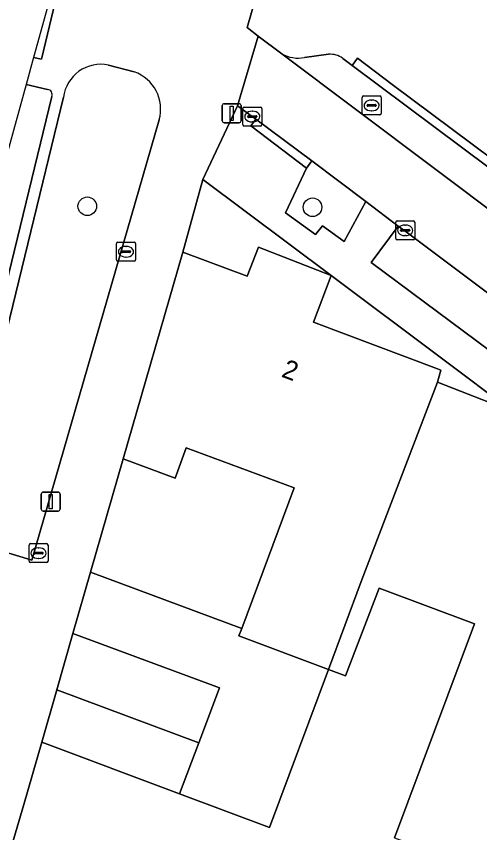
# Model space of a CAD drawing. Extents: x 163266 to 164362, y 381528 to 382286.
# Drawn here: x 163785.25 to 163809.64, y 382121.52 to 382164.49 of the extents above; entities that cross this region are included whole.
import ezdxf

# ---------------------------------------------------------------- set-up
doc = ezdxf.new("R2010")
doc.units = 0
for name, color, linetype in [('IMGEO_Boom', 7, 'Continuous'), ('IMGEO_Erf', 7, 'Continuous'), ('IMGEO_Groenvoorziening', 7, 'Continuous'), ('IMGEO_Kolk', 7, 'Continuous'), ('IMGEO_Lichtmast', 7, 'Continuous'), ('IMGEO_Muur', 7, 'Continuous'), ('IMGEO_Pand', 7, 'Continuous'), ('IMGEO_Pand_nummerreeks', 7, 'Continuous'), ('IMGEO_Parkeervlak_open', 7, 'Continuous'), ('IMGEO_Rijbaan_lokaal_open', 7, 'Continuous'), ('IMGEO_Rioolput', 7, 'Continuous'), ('IMGEO_Voetpad_open', 7, 'Continuous')]:
    doc.layers.add(name, color=color, linetype=linetype)

msp = doc.modelspace()

# ---------------------------------------------------------------- linework, layer by layer
at = {"layer": 'IMGEO_Boom'}
for centre in [(163788.984, 382154.488), (163800.841, 382154.435)]:
    msp.add_circle(centre, 0.489, dxfattribs=at)
at = {"layer": 'IMGEO_Erf'}
for points in [[(163795.065, 382155.894), (163794.02, 382152.073), (163797.406, 382150.806), (163798, 382152.33), (163801.822, 382150.851)], [(163811.358, 382143.691), (163807.624, 382146.494), (163801.822, 382150.851), (163800.894, 382148.381), (163807.412, 382145.926), (163807.598, 382145.856), (163807.41, 382145.221)], [(163797.111, 382132.268), (163799.881, 382139.668), (163794.196, 382141.767), (163793.603, 382140.172), (163790.866, 382141.191), (163789.158, 382135.228)]]:
    msp.add_lwpolyline(points, close=True, dxfattribs=at)
msp.add_lwpolyline([(163805.154, 382121.244), (163809.365, 382132.517), (163804.351, 382134.389), (163802.583, 382129.763), (163801.673, 382130.104), (163798.567, 382121.788), (163793.841, 382123.562), (163786.588, 382126.285), (163785.649, 382122.995), (163778.541, 382098.883)], dxfattribs=at)
at = {"layer": 'IMGEO_Groenvoorziening'}
for points in [[(163822.215, 382162.822), (163823.589, 382169.051), (163800.51, 382174.679), (163797.398, 382163.896), (163797.974, 382163.445), (163799.218, 382162.511)], [(163800.416, 382162.315), (163801.686, 382162.487)], [(163802.427, 382162.272), (163802.92, 382161.904), (163803.211, 382162.276), (163805.031, 382160.907), (163821.881, 382148.329)], [(163791.453, 382161.569), (163790.102, 382161.917)], [(163787.735, 382160.229), (163782.085, 382137.064), (163786.069, 382135.864), (163792.768, 382159.035)]]:
    msp.add_lwpolyline(points, dxfattribs=at)
for points in [[(163803.653, 382154.731), (163800.797, 382156.88), (163800.526, 382156.494), (163799.425, 382154.141), (163800.999, 382153.006), (163801.368, 382153.457), (163802.502, 382152.634)], [(163813.391, 382147.437), (163812.43, 382148.134), (163805.771, 382153.136), (163805.341, 382153.446), (163803.92, 382151.535), (163811.588, 382145.819), (163812.222, 382145.342)]]:
    msp.add_lwpolyline(points, close=True, dxfattribs=at)
for centre, radius, start, end in [((163800.099, 382164.137), 1.85, 241.5525, 279.8642), ((163801.78, 382161.428), 1.063, 52.5446, 95.0954), ((163789.692, 382159.988), 1.972, 78.0108, 172.9775), ((163790.757, 382159.6), 2.088, 344.3099, 70.5435)]:
    msp.add_arc(centre, radius, start, end, dxfattribs=at)
at = {"layer": 'IMGEO_Kolk'}
for p, q in [((163797.168, 382158.785), (163797.168, 382159.637)), ((163797.243, 382159.711), (163798.095, 382159.711)), ((163798.169, 382159.637), (163798.169, 382158.785)), ((163797.427, 382159.205), (163797.427, 382159.217)), ((163797.865, 382159.168), (163797.467, 382159.168)), ((163797.47, 382159.254), (163797.868, 382159.254)), ((163797.656, 382159.491), (163797.681, 382159.491)), ((163797.911, 382159.217), (163797.911, 382159.205)), ((163798.095, 382158.711), (163797.243, 382158.711)), ((163797.679, 382158.931), (163797.654, 382158.931)), ((163805.216, 382152.796), (163805.216, 382153.648)), ((163805.291, 382153.722), (163806.143, 382153.722)), ((163806.217, 382153.648), (163806.217, 382152.796)), ((163805.475, 382153.216), (163805.475, 382153.228)), ((163805.913, 382153.179), (163805.515, 382153.179)), ((163805.518, 382153.265), (163805.916, 382153.265)), ((163805.704, 382153.502), (163805.729, 382153.502)), ((163805.959, 382153.228), (163805.959, 382153.216)), ((163806.143, 382152.722), (163805.291, 382152.722)), ((163805.727, 382152.942), (163805.702, 382152.942)), ((163790.52, 382151.67), (163790.52, 382152.522)), ((163790.595, 382152.596), (163791.447, 382152.596)), ((163791.008, 382152.376), (163791.033, 382152.376)), ((163791.521, 382152.522), (163791.521, 382151.67)), ((163790.779, 382152.09), (163790.779, 382152.102)), ((163791.217, 382152.053), (163790.819, 382152.053)), ((163790.822, 382152.139), (163791.22, 382152.139)), ((163791.031, 382151.816), (163791.006, 382151.816)), ((163791.263, 382152.102), (163791.263, 382152.09)), ((163791.447, 382151.596), (163790.595, 382151.596)), ((163785.918, 382135.804), (163785.918, 382136.656)), ((163785.993, 382136.73), (163786.845, 382136.73)), ((163786.406, 382136.51), (163786.431, 382136.51)), ((163786.919, 382136.656), (163786.919, 382135.804)), ((163786.177, 382136.224), (163786.177, 382136.236)), ((163786.615, 382136.187), (163786.217, 382136.187)), ((163786.22, 382136.273), (163786.618, 382136.273)), ((163786.429, 382135.95), (163786.404, 382135.95)), ((163786.661, 382136.236), (163786.661, 382136.224)), ((163786.845, 382135.73), (163785.993, 382135.73))]:
    msp.add_line(p, q, dxfattribs=at)
for points in [[(163797.168, 382158.785), (163797.168, 382159.637)], [(163797.243, 382159.711), (163798.095, 382159.711)], [(163798.169, 382159.637), (163798.169, 382158.785)], [(163798.095, 382158.711), (163797.243, 382158.711)], [(163805.216, 382152.796), (163805.216, 382153.648)], [(163805.291, 382153.722), (163806.143, 382153.722)], [(163806.217, 382153.648), (163806.217, 382152.796)], [(163806.143, 382152.722), (163805.291, 382152.722)], [(163790.52, 382151.67), (163790.52, 382152.522)], [(163790.595, 382152.596), (163791.447, 382152.596)], [(163791.521, 382152.522), (163791.521, 382151.67)], [(163791.447, 382151.596), (163790.595, 382151.596)], [(163785.918, 382135.804), (163785.918, 382136.656)], [(163785.993, 382136.73), (163786.845, 382136.73)], [(163786.919, 382136.656), (163786.919, 382135.804)], [(163786.845, 382135.73), (163785.993, 382135.73)]]:
    msp.add_lwpolyline(points, dxfattribs=at)
for centre, radius, start, end in [((163797.245, 382159.635), 0.0765, 91.552, 178.448), ((163797.245, 382159.635), 0.0765, 91.552, 178.448), ((163798.093, 382159.635), 0.0765, 1.552, 88.448), ((163798.093, 382159.635), 0.0765, 1.552, 88.448), ((163797.467, 382159.214), 0.0403, 85.8775, 175.7526), ((163797.464, 382159.204), 0.0366, 178.938, 274.7102), ((163797.868, 382159.211), 0.043, 264.8664, 352.4533), ((163797.872, 382159.216), 0.0386, 1.7309, 96.639), ((163797.245, 382158.787), 0.0765, 181.552, 268.448), ((163797.245, 382158.787), 0.0765, 181.552, 268.448), ((163798.093, 382158.787), 0.0765, 271.552, 358.448), ((163798.093, 382158.787), 0.0765, 271.552, 358.448), ((163805.293, 382153.646), 0.0765, 91.552, 178.448), ((163805.293, 382153.646), 0.0765, 91.552, 178.448), ((163806.141, 382153.646), 0.0765, 1.552, 88.448), ((163806.141, 382153.646), 0.0765, 1.552, 88.448), ((163805.515, 382153.225), 0.0403, 85.8775, 175.7526), ((163805.512, 382153.215), 0.0366, 178.938, 274.7102), ((163805.916, 382153.222), 0.043, 264.8664, 352.4533), ((163805.92, 382153.227), 0.0386, 1.7309, 96.639), ((163805.293, 382152.798), 0.0765, 181.552, 268.448), ((163805.293, 382152.798), 0.0765, 181.552, 268.448), ((163806.141, 382152.798), 0.0765, 271.552, 358.448), ((163806.141, 382152.798), 0.0765, 271.552, 358.448), ((163790.597, 382152.52), 0.0765, 91.552, 178.448), ((163790.597, 382152.52), 0.0765, 91.552, 178.448), ((163791.445, 382152.52), 0.0765, 1.552, 88.448), ((163791.445, 382152.52), 0.0765, 1.552, 88.448), ((163790.819, 382152.099), 0.0403, 85.8775, 175.7526), ((163790.816, 382152.089), 0.0366, 178.938, 274.7102), ((163791.22, 382152.096), 0.043, 264.8664, 352.4533), ((163791.224, 382152.101), 0.0386, 1.7309, 96.639), ((163790.597, 382151.672), 0.0765, 181.552, 268.448), ((163790.597, 382151.672), 0.0765, 181.552, 268.448), ((163791.445, 382151.672), 0.0765, 271.552, 358.448), ((163791.445, 382151.672), 0.0765, 271.552, 358.448), ((163785.995, 382136.654), 0.0765, 91.552, 178.448), ((163785.995, 382136.654), 0.0765, 91.552, 178.448), ((163786.843, 382136.654), 0.0765, 1.552, 88.448), ((163786.843, 382136.654), 0.0765, 1.552, 88.448), ((163786.217, 382136.233), 0.0403, 85.8775, 175.7526), ((163786.214, 382136.223), 0.0366, 178.938, 274.7102), ((163786.618, 382136.23), 0.043, 264.8664, 352.4533), ((163786.622, 382136.235), 0.0386, 1.7309, 96.639), ((163785.995, 382135.806), 0.0765, 181.552, 268.448), ((163785.995, 382135.806), 0.0765, 181.552, 268.448), ((163786.843, 382135.806), 0.0765, 271.552, 358.448), ((163786.843, 382135.806), 0.0765, 271.552, 358.448)]:
    msp.add_arc(centre, radius, start, end, dxfattribs=at)
for centre, major_axis, ratio, start_param, end_param in [((163797.655, 382159.211), (-0.387, 0.002), 0.722429, 4.712389, 7.853982), ((163797.68, 382159.211), (-0.39, 0.002), 0.717154, 1.570796, 4.712389), ((163805.703, 382153.222), (-0.387, 0.002), 0.722429, 4.712389, 7.853982), ((163805.728, 382153.222), (-0.39, 0.002), 0.717154, 1.570796, 4.712389), ((163791.007, 382152.096), (-0.387, 0.002), 0.722429, 4.712389, 7.853982), ((163791.032, 382152.096), (-0.39, 0.002), 0.717154, 1.570796, 4.712389), ((163786.405, 382136.23), (-0.387, 0.002), 0.722429, 4.712389, 7.853982), ((163786.43, 382136.23), (-0.39, 0.002), 0.717154, 1.570796, 4.712389)]:
    msp.add_ellipse(centre, major_axis=major_axis, ratio=ratio, start_param=start_param, end_param=end_param, dxfattribs=at)
at = {"layer": 'IMGEO_Lichtmast'}
for p, q in [((163796.086, 382158.986), (163796.086, 382159.786)), ((163796.086, 382159.786), (163796.086, 382158.986)), ((163796.186, 382159.886), (163796.976, 382159.886)), ((163796.976, 382159.886), (163796.186, 382159.886)), ((163797.076, 382159.786), (163797.076, 382158.986)), ((163797.076, 382158.986), (163797.076, 382159.786)), ((163796.976, 382158.886), (163796.186, 382158.886)), ((163796.186, 382158.886), (163796.976, 382158.886)), ((163786.661, 382139.442), (163787.451, 382139.442)), ((163787.451, 382139.442), (163786.661, 382139.442)), ((163786.561, 382138.542), (163786.561, 382139.342)), ((163786.561, 382139.342), (163786.561, 382138.542)), ((163787.551, 382139.342), (163787.551, 382138.542)), ((163787.551, 382138.542), (163787.551, 382139.342)), ((163787.451, 382138.442), (163786.661, 382138.442)), ((163786.661, 382138.442), (163787.451, 382138.442))]:
    msp.add_line(p, q, dxfattribs=at)
for points in [[(163796.506, 382159.761), (163796.656, 382159.761), (163796.656, 382159.011), (163796.506, 382159.011), (163796.506, 382159.761)], [(163786.981, 382139.317), (163787.131, 382139.317), (163787.131, 382138.567), (163786.981, 382138.567), (163786.981, 382139.317)]]:
    msp.add_lwpolyline(points, dxfattribs=at)
for centre, start, end in [((163796.186, 382159.786), 90, 180), ((163796.186, 382159.786), 90, 180), ((163796.976, 382159.786), 0, 90), ((163796.976, 382159.786), 360, 90), ((163796.186, 382158.986), 180, 270), ((163796.186, 382158.986), 180, 270), ((163796.976, 382158.986), 270, 0), ((163796.976, 382158.986), 270, 0), ((163786.661, 382139.342), 90, 180), ((163786.661, 382139.342), 90, 180), ((163787.451, 382139.342), 0, 90), ((163787.451, 382139.342), 360, 90), ((163786.661, 382138.542), 180, 270), ((163786.661, 382138.542), 180, 270), ((163787.451, 382138.542), 270, 0), ((163787.451, 382138.542), 270, 0)]:
    msp.add_arc(centre, 0.1, start, end, dxfattribs=at)
at = {"layer": 'IMGEO_Muur'}
msp.add_lwpolyline([(163790.866, 382141.191), (163789.158, 382135.228)], dxfattribs=at)
at = {"layer": 'IMGEO_Pand'}
for points in [[(163797.111, 382132.268), (163796.961, 382131.869), (163801.673, 382130.104), (163803.405, 382134.742), (163807.41, 382145.221), (163807.598, 382145.856), (163807.412, 382145.926), (163800.894, 382148.381), (163801.822, 382150.851), (163798, 382152.33), (163797.406, 382150.806), (163794.02, 382152.073), (163790.866, 382141.191), (163793.603, 382140.172), (163794.196, 382141.767), (163799.881, 382139.668)], [(163816.992, 382138.232), (163817.143, 382138.733), (163816.636, 382138.922), (163810.412, 382141.246), (163811.358, 382143.691), (163807.41, 382145.221), (163803.405, 382134.742), (163801.673, 382130.104), (163802.583, 382129.763), (163804.351, 382134.389), (163809.365, 382132.517), (163805.154, 382121.244), (163809.909, 382119.463), (163811.978, 382124.968)], [(163797.111, 382132.268), (163789.158, 382135.228), (163788.231, 382132.003), (163795.936, 382129.134), (163794.852, 382126.252), (163793.841, 382123.562), (163798.567, 382121.788), (163801.673, 382130.104), (163796.961, 382131.869)], [(163787.378, 382129.035), (163794.852, 382126.252), (163795.936, 382129.134), (163788.231, 382132.003)], [(163787.378, 382129.035), (163786.588, 382126.285), (163793.841, 382123.562), (163794.852, 382126.252)]]:
    msp.add_lwpolyline(points, close=True, dxfattribs=at)
at = {"layer": 'IMGEO_Parkeervlak_open'}
for points in [[(163799.218, 382162.511), (163823.05, 382144.613)], [(163801.686, 382162.487), (163800.416, 382162.315)], [(163821.709, 382147.869), (163802.92, 382161.904), (163802.427, 382162.272)], [(163785.77, 382160.905), (163781.021, 382143.687), (163779.576, 382137.77), (163781.529, 382137.299), (163787.113, 382160.27)], [(163786.898, 382160.642), (163785.77, 382160.905)]]:
    msp.add_lwpolyline(points, dxfattribs=at)
for centre, radius, start, end in [((163800.099, 382164.137), 1.85, 241.5525, 279.8642), ((163801.78, 382161.428), 1.063, 52.5446, 95.0954), ((163786.853, 382160.368), 0.278, 339.4096, 80.6425)]:
    msp.add_arc(centre, radius, start, end, dxfattribs=at)
at = {"layer": 'IMGEO_Rijbaan_lokaal_open'}
for points in [[(163799.218, 382162.511), (163797.974, 382163.445), (163796.89, 382159.778), (163797.67, 382159.212), (163797.85, 382159.068), (163800.797, 382156.88), (163803.653, 382154.731), (163805.341, 382153.446), (163805.771, 382153.136), (163812.43, 382148.134), (163813.391, 382147.437), (163815.074, 382146.189), (163822.111, 382140.937), (163823.903, 382139.611), (163825.622, 382138.317), (163832.053, 382133.523), (163833.763, 382132.26), (163838.026, 382129.075), (163838.23, 382128.937), (163840.477, 382138.242), (163838.57, 382139.664), (163835.492, 382141.96), (163832.689, 382144.051)], [(163826.261, 382142.223), (163824.013, 382143.896), (163823.05, 382144.613), (163799.218, 382162.511)]]:
    msp.add_lwpolyline(points, dxfattribs=at)
at = {"layer": 'IMGEO_Rioolput'}
for p, q in [((163803.449, 382159.37), (163803.449, 382160.222)), ((163803.524, 382160.296), (163804.376, 382160.296)), ((163803.937, 382160.076), (163803.962, 382160.076)), ((163804.45, 382160.222), (163804.45, 382159.37)), ((163803.708, 382159.79), (163803.708, 382159.802)), ((163804.146, 382159.753), (163803.748, 382159.753)), ((163803.751, 382159.839), (163804.149, 382159.839)), ((163804.192, 382159.802), (163804.192, 382159.79)), ((163804.376, 382159.296), (163803.524, 382159.296)), ((163803.96, 382159.516), (163803.935, 382159.516))]:
    msp.add_line(p, q, dxfattribs=at)
for points in [[(163803.449, 382159.37), (163803.449, 382160.222)], [(163803.524, 382160.296), (163804.376, 382160.296)], [(163804.45, 382160.222), (163804.45, 382159.37)], [(163804.376, 382159.296), (163803.524, 382159.296)]]:
    msp.add_lwpolyline(points, dxfattribs=at)
for centre, radius, start, end in [((163803.526, 382160.22), 0.0765, 91.552, 178.448), ((163803.526, 382160.22), 0.0765, 91.552, 178.448), ((163804.374, 382160.22), 0.0765, 1.552, 88.448), ((163804.374, 382160.22), 0.0765, 1.552, 88.448), ((163803.748, 382159.799), 0.0403, 85.8775, 175.7526), ((163803.745, 382159.789), 0.0366, 178.938, 274.7102), ((163804.149, 382159.796), 0.043, 264.8664, 352.4533), ((163804.153, 382159.801), 0.0386, 1.7309, 96.639), ((163803.526, 382159.372), 0.0765, 181.552, 268.448), ((163803.526, 382159.372), 0.0765, 181.552, 268.448), ((163804.374, 382159.372), 0.0765, 271.552, 358.448), ((163804.374, 382159.372), 0.0765, 271.552, 358.448)]:
    msp.add_arc(centre, radius, start, end, dxfattribs=at)
for centre, major_axis, ratio, start_param, end_param in [((163803.936, 382159.796), (-0.387, 0.002), 0.722429, 4.712389, 7.853982), ((163803.961, 382159.796), (-0.39, 0.002), 0.717154, 1.570796, 4.712389)]:
    msp.add_ellipse(centre, major_axis=major_axis, ratio=ratio, start_param=start_param, end_param=end_param, dxfattribs=at)
at = {"layer": 'IMGEO_Voetpad_open'}
for points in [[(163790.269, 382177.214), (163788.292, 382170.048), (163788.441, 382170.011), (163786.576, 382162.224), (163786.159, 382162.315), (163785.77, 382160.905), (163786.898, 382160.642)], [(163778.541, 382098.883), (163785.649, 382122.995), (163786.588, 382126.285), (163787.378, 382129.035), (163788.231, 382132.003), (163789.158, 382135.228), (163790.866, 382141.191), (163794.02, 382152.073), (163795.065, 382155.894), (163796.89, 382159.778), (163797.974, 382163.445), (163797.398, 382163.896), (163800.51, 382174.679), (163801.236, 382176.594)], [(163821.881, 382148.329), (163805.031, 382160.907), (163803.211, 382162.276), (163802.92, 382161.904), (163821.709, 382147.869)], [(163790.102, 382161.917), (163791.453, 382161.569)], [(163787.113, 382160.27), (163781.529, 382137.299), (163779.256, 382128.438), (163777.945, 382123.231), (163776.669, 382118.455), (163773.695, 382107.305)], [(163792.768, 382159.035), (163786.069, 382135.864), (163782.085, 382137.064), (163787.735, 382160.229)], [(163811.588, 382145.819), (163803.92, 382151.535), (163805.341, 382153.446), (163803.653, 382154.731), (163802.502, 382152.634), (163801.368, 382153.457), (163800.999, 382153.006), (163799.425, 382154.141), (163800.526, 382156.494), (163797.591, 382158.728), (163797.85, 382159.068), (163797.67, 382159.212), (163796.89, 382159.778), (163795.065, 382155.894), (163801.822, 382150.851), (163807.624, 382146.494), (163811.358, 382143.691)]]:
    msp.add_lwpolyline(points, dxfattribs=at)
for points in [[(163788.292, 382170.048), (163786.159, 382162.315), (163786.576, 382162.224), (163788.441, 382170.011)], [(163800.797, 382156.88), (163797.85, 382159.068), (163797.591, 382158.728), (163800.526, 382156.494)]]:
    msp.add_lwpolyline(points, close=True, dxfattribs=at)
for centre, radius, start, end in [((163789.692, 382159.988), 1.972, 78.0108, 172.9775), ((163790.757, 382159.6), 2.088, 344.3099, 70.5435), ((163786.853, 382160.368), 0.278, 339.4096, 80.6425)]:
    msp.add_arc(centre, radius, start, end, dxfattribs=at)

# ---------------------------------------------------------------- texts
at = {"layer": 'IMGEO_Pand_nummerreeks'}
msp.add_text('2', height=1, rotation=339.3616, dxfattribs=at).set_placement((163799.156, 382145.531))

doc.saveas('drawing.dxf')
